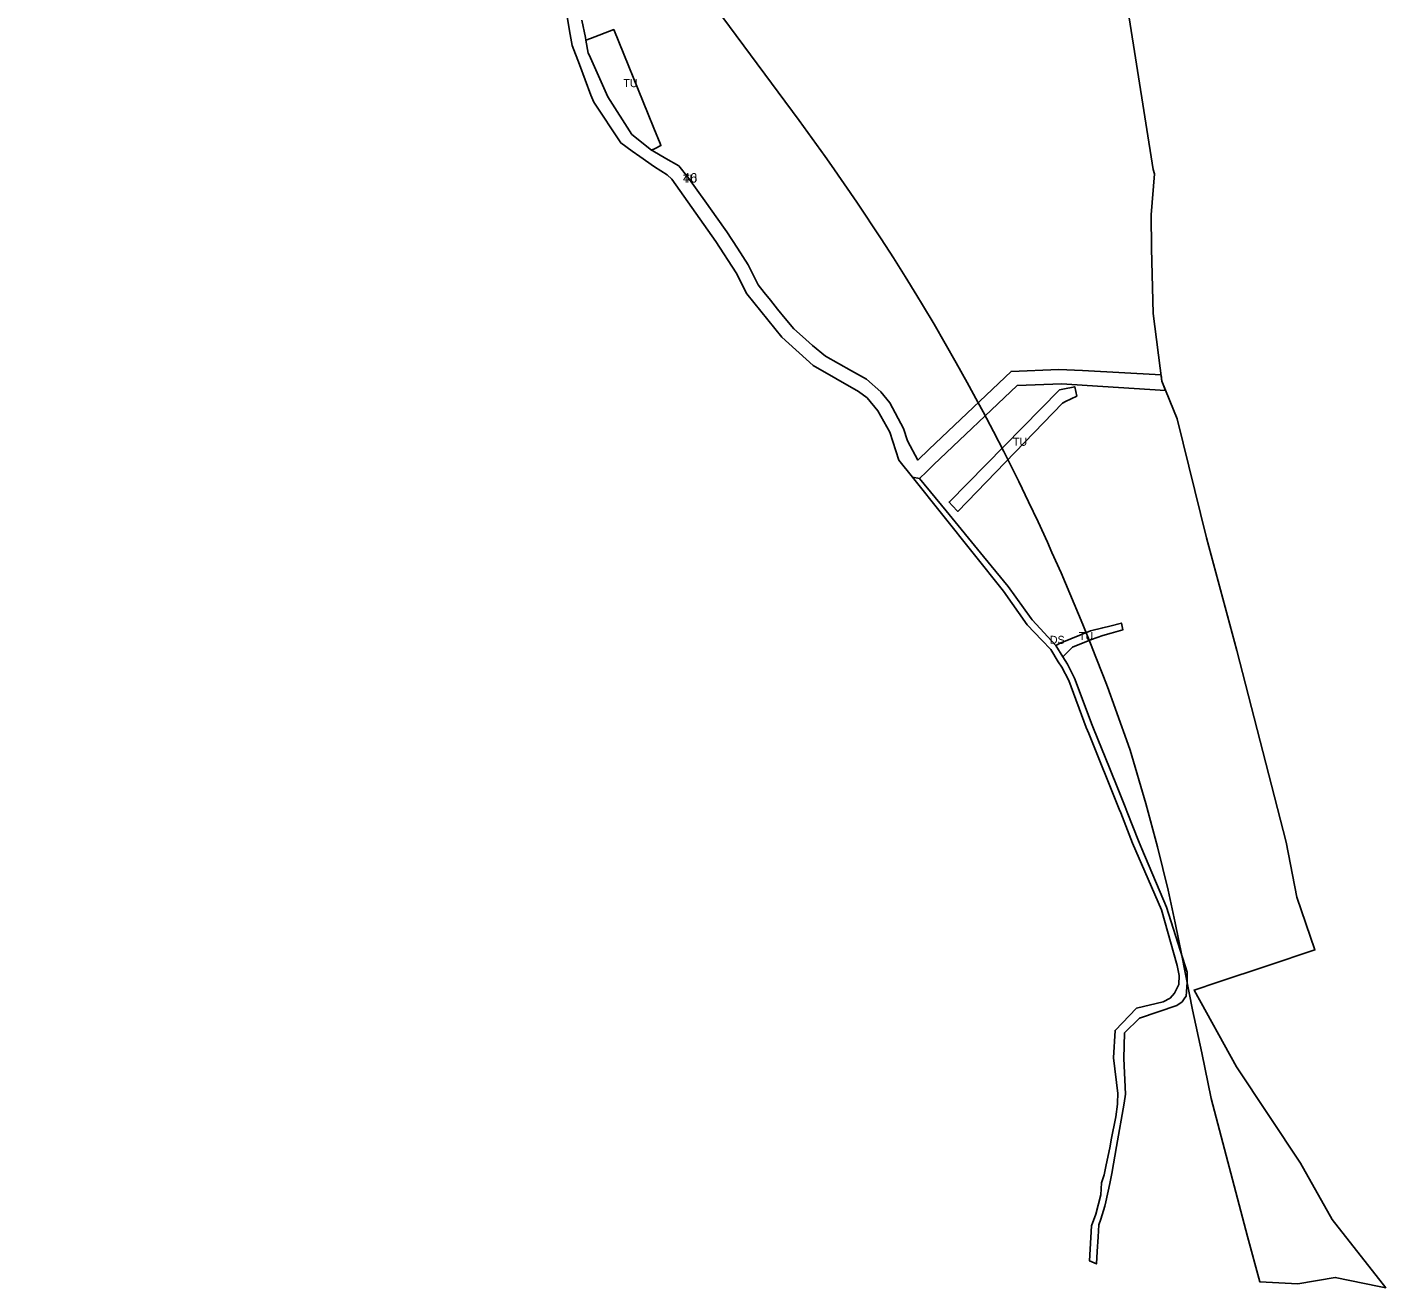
# Model space of a CAD drawing. Extents: x -535435 to -532834, y -1165802 to -1163866.
# Drawn here: x -533683 to -532834, y -1165802 to -1165015 of the extents above; entities that cross this region are included whole.
import ezdxf

# ---------------------------------------------------------------- set-up
doc = ezdxf.new("R2010")
doc.units = 0
for name, color, linetype in [('90320013', 7, 'Continuous'), ('90350033', 7, 'Continuous'), ('90380013', 7, 'Continuous'), ('90380023', 7, 'Continuous'), ('ID_navrh', 7, 'Continuous')]:
    doc.layers.add(name, color=color, linetype=linetype)

msp = doc.modelspace()

# ---------------------------------------------------------------- linework, layer by layer
at = {"layer": '90320013'}
msp.add_lwpolyline([(-533129.6, -1165295.975), (-533125.24, -1165296.69), (-533125.197, -1165296.649), (-533108.53, -1165316.98), (-533085.21, -1165345.43), (-533069.91, -1165364.08), (-533055.45, -1165384.16), (-533054.81, -1165385.05), (-533040.077, -1165401.03), (-533035.604, -1165408.177), (-533032.833, -1165412.606), (-533028.308, -1165421.343), (-533017.262, -1165450.818), (-533016.451, -1165452.825), (-533006.526, -1165477.375), (-533000.91, -1165491.266), (-532996.663, -1165501.772), (-532995.402, -1165504.997), (-532988.358, -1165523.01), (-532986.264, -1165527.956), (-532970.84, -1165564.38), (-532958.061, -1165604.931), (-532957.99, -1165611.29), (-532958.57, -1165619.96), (-532959.419, -1165621.155), (-532961.17, -1165623.62), (-532964.45, -1165625.74), (-532987.76, -1165633.74), (-532997.2, -1165643), (-532997.56, -1165658.85), (-532996.45, -1165681.15), (-532997.44, -1165686.82), (-533002.12, -1165713.97), (-533005.03, -1165730.85), (-533006.36, -1165737.02), (-533008.83, -1165748.52), (-533009.41, -1165751.23), (-533011.98, -1165759.36), (-533013.08, -1165762.85), (-533013.56, -1165770.31), (-533014.15, -1165779.42), (-533014.65, -1165787.24), (-533018.93, -1165785.38), (-533017.76, -1165763.5), (-533015, -1165756.19), (-533011.87, -1165744.03), (-533011.45, -1165736.54), (-533009.87, -1165731.53), (-533008.79, -1165726.42), (-533006.19, -1165713.61), (-533005.43, -1165709.83), (-533002.65, -1165695.46), (-533001.54, -1165687.53), (-533001.5, -1165686.54), (-533001.3, -1165680.76), (-533004.03, -1165658.51), (-533003.06, -1165641.42), (-532989.74, -1165627.54), (-532973.06, -1165623.55), (-532968.68, -1165621.36), (-532966.01, -1165618.23), (-532963.13, -1165612.63), (-532963.1, -1165607.05), (-532964.35, -1165600.88), (-532973.97, -1165566.03), (-532982.326, -1165546.856), (-532992.09, -1165524.45), (-532999.491, -1165505.524), (-533000.38, -1165503.25), (-533019.481, -1165456.002), (-533020.99, -1165452.27), (-533031.97, -1165422.97), (-533036.31, -1165414.59), (-533038.485, -1165411.114), (-533043.25, -1165403.5), (-533048.833, -1165397.671), (-533057.97, -1165388.13), (-533072.82, -1165367.05)], close=True, dxfattribs=at)
at = {"layer": '90350033'}
msp.add_lwpolyline([(-532994.2, -1165009.04), (-532979.21, -1165103.79), (-532978.36, -1165106.4), (-532980.41, -1165132.1), (-532980.24, -1165153.13), (-532979.22, -1165193.65), (-532973.81, -1165236.01), (-532964.21, -1165259.48), (-532945.97, -1165333.71), (-532926.98, -1165404.07), (-532896.21, -1165523.88), (-532889.53, -1165558.14), (-532878.16, -1165591.08), (-532908.13, -1165601.07), (-532938.91, -1165611.34), (-532953.65, -1165616.26), (-532927.21, -1165664.12), (-532887.26, -1165724.36), (-532867.49, -1165759.55), (-532833.91, -1165802.16), (-532838.03, -1165801.32), (-532865.54, -1165795.7), (-532888.93, -1165799.76), (-532912.703, -1165798.369), (-532920.278, -1165770.201), (-532943.056, -1165683.939), (-532948.943, -1165655.5), (-532954.573, -1165628.489), (-532961.392, -1165594.52), (-532965.489, -1165574.118), (-532969.871, -1165553.8), (-532976.524, -1165526.776), (-532983.729, -1165499.778), (-532993.697, -1165466.326), (-532995.938, -1165459.839), (-533000.636, -1165446.556), (-533002.973, -1165440.096), (-533007.863, -1165426.874), (-533010.293, -1165420.451), (-533015.377, -1165407.297), (-533017.9, -1165400.907), (-533023.174, -1165387.826), (-533025.791, -1165381.471), (-533031.23, -1165368.523), (-533036.77, -1165355.684), (-533042.459, -1165342.843), (-533045.287, -1165336.582), (-533051.159, -1165323.827), (-533057.127, -1165311.188), (-533063.217, -1165298.607), (-533069.451, -1165286.036), (-533072.544, -1165279.911), (-533078.957, -1165267.437), (-533085.486, -1165255.031), (-533088.724, -1165248.986), (-533095.428, -1165236.683), (-533102.217, -1165224.504), (-533109.118, -1165212.398), (-533116.133, -1165200.365), (-533123.288, -1165188.356), (-533126.829, -1165182.51), (-533134.149, -1165170.618), (-533141.546, -1165158.856), (-533149.081, -1165147.123), (-533152.806, -1165141.414), (-533160.53, -1165129.758), (-533164.331, -1165124.111), (-533172.179, -1165112.63), (-533180.127, -1165101.238), (-533184.053, -1165095.696), (-533192.152, -1165084.433), (-533200.383, -1165073.214), (-533682.598, -1164422.461)], dxfattribs=at)
at = {"layer": '90380013'}
for points in [[(-533333.62, -1165022.99), (-533330.632, -1165021.862), (-533316.16, -1165016.4), (-533294.68, -1165069.27), (-533291.2, -1165077.84), (-533287.25, -1165087.56), (-533286.76, -1165088.76), (-533290.36, -1165090.63), (-533292.517, -1165091.744), (-533304.875, -1165081.833), (-533319.895, -1165058.356), (-533331.65, -1165032.22), (-533332.19, -1165031.01)], [(-533035.573, -1165240.864), (-533028.21, -1165239.43), (-533026.975, -1165245.213), (-533033.915, -1165248.628), (-533035.85, -1165249.58), (-533101.358, -1165317.299), (-533104.858, -1165313.507), (-533106.758, -1165311.449), (-533037.66, -1165241.27)], [(-533040.077, -1165401.03), (-533037.36, -1165399.59), (-533018.33, -1165391.89), (-533010.77, -1165389.96), (-533006.318, -1165388.853), (-532999.025, -1165387.039), (-532998.242, -1165391.325), (-533005.487, -1165393.393), (-533010.59, -1165394.85), (-533017.717, -1165397.177), (-533017.82, -1165397.21), (-533029.664, -1165402.123), (-533035.604, -1165408.177)]]:
    msp.add_lwpolyline(points, close=True, dxfattribs=at)
at = {"layer": '90380023'}
msp.add_lwpolyline([(-533336.164, -1165010.56), (-533333.91, -1165021.36), (-533333.62, -1165022.99), (-533332.19, -1165031.01), (-533331.65, -1165032.22), (-533319.895, -1165058.356), (-533304.875, -1165081.833), (-533292.517, -1165091.744), (-533291.871, -1165092.117), (-533283.754, -1165096.808), (-533275.616, -1165101.51), (-533269.885, -1165108.505), (-533264.059, -1165116.707), (-533258.331, -1165124.77), (-533252.308, -1165133.249), (-533245.578, -1165142.723), (-533238.958, -1165152.798), (-533232.175, -1165163.211), (-533225.922, -1165175.806), (-533222.253, -1165180.637), (-533218.343, -1165185.445), (-533213.92, -1165190.884), (-533209.065, -1165196.853), (-533203.683, -1165203.151), (-533198.238, -1165208.072), (-533192.12, -1165213.6), (-533183.904, -1165220.221), (-533167.647, -1165229.437), (-533158.312, -1165234.728), (-533149.315, -1165242.562), (-533143.803, -1165249.375), (-533135.154, -1165265.393), (-533132.616, -1165273.134), (-533126.238, -1165285.22), (-533119.066, -1165278.401), (-533067.971, -1165229.821), (-533038.193, -1165228.594), (-533023.406, -1165229.36), (-532974.335, -1165231.899), (-532973.81, -1165236.01), (-532971.48, -1165241.706), (-533020.388, -1165238.55), (-533036.286, -1165237.524), (-533064.221, -1165238.674), (-533116.373, -1165288.26), (-533120.847, -1165292.513), (-533125.197, -1165296.649), (-533125.24, -1165296.69), (-533129.6, -1165295.975), (-533138.08, -1165285.36), (-533143.81, -1165267.88), (-533151.29, -1165254.43), (-533157.9, -1165246.26), (-533163.24, -1165242.28), (-533191.59, -1165226.21), (-533211.21, -1165208.48), (-533233.16, -1165181.49), (-533239.66, -1165168.21), (-533252.35, -1165148.73), (-533279.97, -1165109.85), (-533282.89, -1165106.98), (-533290.68, -1165102.01), (-533299.889, -1165095.558), (-533304.665, -1165092.211), (-533311.86, -1165087.17), (-533328.63, -1165061.62), (-533330.525, -1165057.282), (-533337.57, -1165038.08), (-533342.183, -1165026.234), (-533343.416, -1165019.324), (-533350.73, -1164975.81)], dxfattribs=at)

# ---------------------------------------------------------------- texts
at = {"layer": '90320013'}
msp.add_text('DS', height=5, rotation=360, dxfattribs=at).set_placement((-533043.795, -1165399.9641))
at = {"layer": '90380013'}
for rotation, p in [(360, (-533310.19, -1165052.3099)), (0.0000001, (-533066.8665, -1165276.2884)), (0, (-533025.6206, -1165397.608))]:
    msp.add_text('TU', height=5, rotation=rotation, dxfattribs=at).set_placement(p)
at = {"layer": '90380023'}
msp.add_text('TU', height=5, rotation=360, dxfattribs=at).set_placement((-533272.9549, -1165111.9545))
at = {"layer": 'ID_navrh'}
msp.add_text('46', height=6, rotation=360, dxfattribs=at).set_placement((-533272.9549, -1165111.9545))

doc.saveas('drawing.dxf')
